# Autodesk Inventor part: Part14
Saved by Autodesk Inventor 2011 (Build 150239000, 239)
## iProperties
Created: 2010-10
Part Number: Part14
Document SubType Name: Modeling
Designer: tribel
Density: 1 g/cm^3
Author: tribel
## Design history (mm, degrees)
feature "Base1"
body "Solid1"
